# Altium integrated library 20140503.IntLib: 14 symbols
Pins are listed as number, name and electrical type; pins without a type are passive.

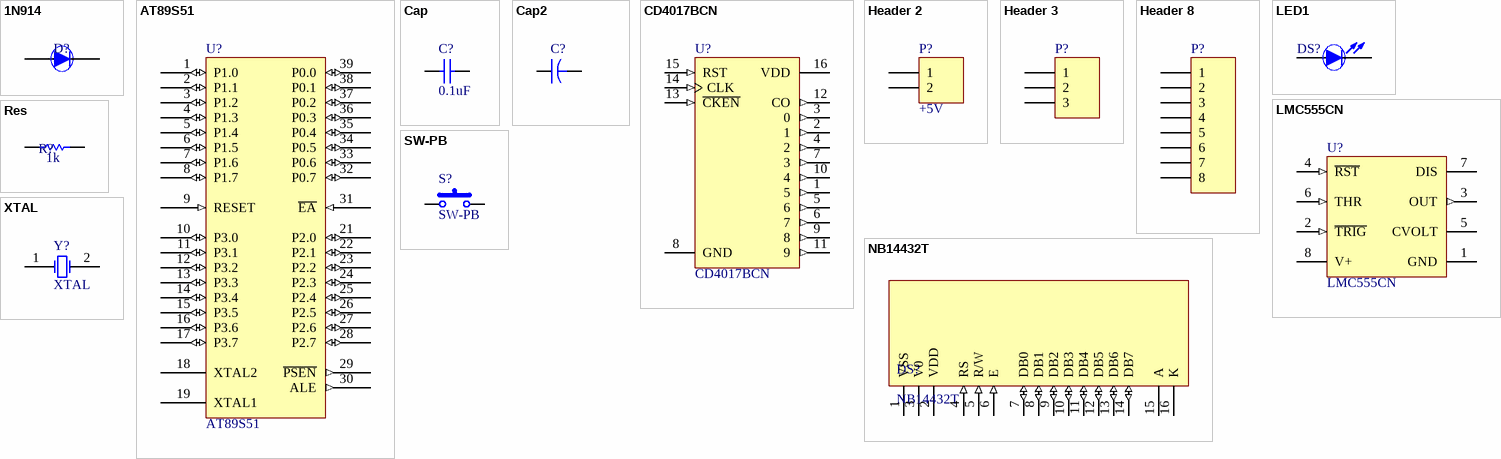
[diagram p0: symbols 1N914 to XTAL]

## 1N914
designator D?  (value not drawn)
High Conductance Fast Diode
footprint D400
simulation model 1N914 (DIODE)
signal-integrity model 1N914
footprint D400-1
pins: 1 A, 2 K

## AT89S51
designator U?
footprint DIP40_8051 (40 pin 雙併排包裝)
pins: 1 P1.0 (io), 2 P1.1 (io), 3 P1.2 (io), 4 P1.3 (io), 5 P1.4 (io), 6 P1.5 (io), 7 P1.6 (io), 8 P1.7 (io), 9 RESET (in), 10 P3.0 (io), 11 P3.1 (io), 12 P3.2 (io), 13 P3.3 (io), 14 P3.4 (io), 15 P3.5 (io), 16 P3.6 (io), 17 P3.7 (io), 18 XTAL2, 19 XTAL1, 20 GND (power) hidden to GND, 21 P2.0 (io), 22 P2.1 (io), 23 P2.2 (io), 24 P2.3 (io), 25 P2.4 (io), 26 P2.5 (io), 27 P2.6 (io), 28 P2.7 (io), 29 ~{PSEN} (out), 30 ALE (out), 31 ~{EA} (in), 32 P0.7 (io), 33 P0.6 (io), 34 P0.5 (io), 35 P0.4 (io), 36 P0.3 (io), 37 P0.2 (io), 38 P0.1 (io), 39 P0.0 (io), 40 VCC (power) hidden to VCC

## Cap
designator C?  value 0.1uF  (hidden comment: Cap)
Capacitor
simulation model CAP (Capacitor)
signal-integrity model Cap
footprint C200 - 1 (陶瓷電容器)
simulation model CAP (Default semiconductor capacitor)
pins: 1, 2

## Cap2
designator C?
Capacitor
footprint CAP-260-1
pins: 1, 2

## CD4017BCN
designator U?
Decade Counter/Divider with 10 Decoded Outputs
3D model N16E (DIP, 16-Pin, Row Spacing 7.62 mm, Pitch 2.54 mm)
simulation model 4017 (SIMCODE)
footprint DIP16_4017 (4017)
pins: 1 5 (out), 2 1 (out), 3 0 (out), 4 2 (out), 5 6 (out), 6 7 (out), 7 3 (out), 8 GND (power), 9 8 (out), 10 4 (out), 11 9 (out), 12 CO (out), 13 ~{CKEN} (in), 14 CLK (in), 15 RST (in), 16 VDD (power)

## Header 2
designator P?, comment +5V
Header, 2-Pin
footprint HEADER 2 PW-0.2
signal-integrity model Connector
footprint HDR1X2 (2pin針腳/座)
pins: 1, 2

## Header 3
designator P?
Header, 3-Pin
footprint HDR1X3 (Footprint not found)
signal-integrity model Connector
pins: 1, 2, 3

## Header 8
designator P?
Header, 8-Pin
footprint HDR1X8 (Connector; Header; 8 Position)
signal-integrity model Connector
pins: 1, 2, 3, 4, 5, 6, 7, 8

## LED1
designator DS?  (value not drawn)
Typical RED GaAs LED
footprint LED-3mm_G (3mm LED_Green)
simulation model LED1 (Typ RED GaAs LED: Vf=1.7V Vr=4V If=40mA trr=3uS)
pins: 1 A, 2 K

## LMC555CN
designator U?
CMOS Timer; Manufacturer: National Semiconductor; CompType: Analog IC; PackageTopMarking: NSUZXYTT*LMC*555CN; PowerWise: N
footprint N08E_555
simulation model 555 (555 MCE)
pins: 1 GND (power), 2 ~{TRIG} (in), 3 OUT (out), 4 ~{RST} (in), 5 CVOLT, 6 THR (in), 7 DIS (oc), 8 V+ (power)

## NB14432T
designator DS?
中文LCD模組
footprint LCM_16
pins: 1 VSS (power), 2 VDD (power), 3 V0, 4 RS (in), 5 R/W (in), 6 E (in), 7 DB0 (io), 8 DB1 (io), 9 DB2 (io), 10 DB3 (io), 11 DB4 (io), 12 DB5 (io), 13 DB6 (io), 14 DB7 (io), 15 A, 16 K

## Res
designator R?, comment 1k
Resistor
footprint AXIAL-0.3 (Axial Device, Thru-Hole; 2 Leads; 0.3 in Pin Spacing)
simulation model RESISTOR (Resistor)
signal-integrity model Res
pins: 1, 2

## SW-PB
designator S?
Switch
footprint TACK6
pins: 1, 2

## XTAL
designator Y?
Crystal Oscillator
footprint XTAL4-8
pins: 1 OSC1, 2 OSC2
